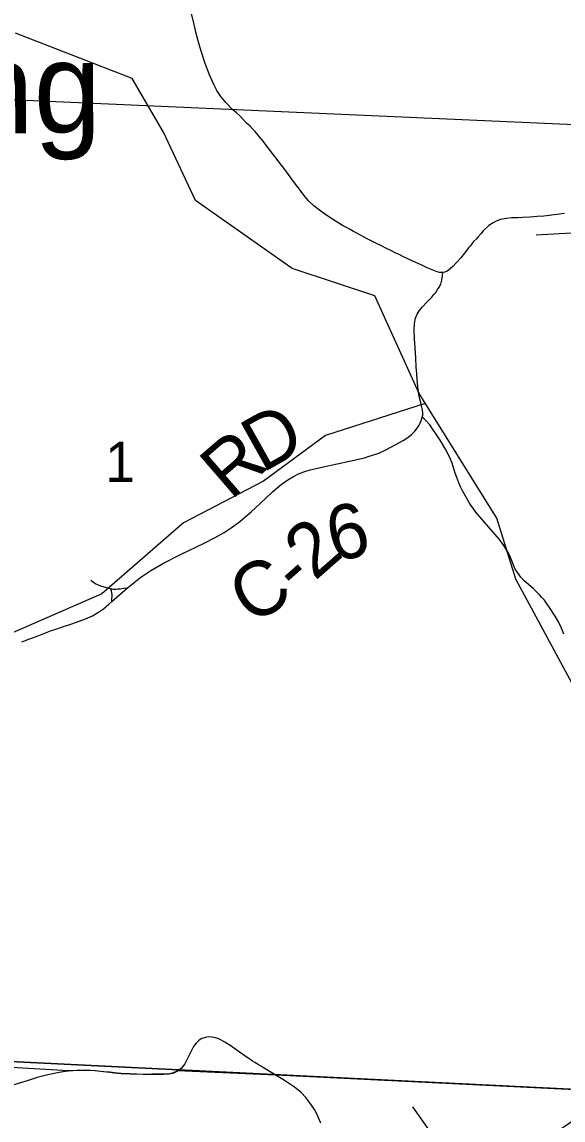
# Model space of a CAD drawing. Extents: x 396.2 to 468.4, y 232.6 to 279.1.
# Drawn here: x 421.28 to 421.844, y 276.238 to 277.383 of the extents above; entities that cross this region are included whole.
import ezdxf

# ---------------------------------------------------------------- set-up
doc = ezdxf.new("R2010")
doc.units = 0
for name, color, linetype in [('Default', 7, 'Continuous'), ('GM_X_County_Road', 7, 'Continuous'), ('GM_X_County_Road_Text', 7, 'Continuous'), ('GM_X_Minor_River', 7, 'Continuous'), ('GM_X_Minor_River_Text', 7, 'Continuous'), ('GM_X_Section', 7, 'Continuous'), ('GM_X_Section_Text', 7, 'Continuous'), ('GM_X_Township', 7, 'Continuous'), ('GM_X_Township_Road', 7, 'Continuous')]:
    doc.layers.add(name, color=color, linetype=linetype)

msp = doc.modelspace()

# ---------------------------------------------------------------- linework, layer by layer
at = {"layer": 'Default'}
msp.add_lwpolyline([(420.82, 276.3196), (421.3281, 276.2897), (421.3374, 276.2902), (421.3462, 276.2904), (421.3559, 276.2899), (421.3682, 276.2886), (421.3714, 276.2883), (421.3763, 276.2876), (421.3831, 276.287), (421.3924, 276.2866), (421.4063, 276.2861), (421.4152, 276.2862), (421.4272, 276.2863), (421.4332, 276.2865), (421.4379, 276.2877), (421.4411, 276.2892), (421.4419, 276.2897), (421.5448, 276.2853), (421.871, 276.2694), (421.9162, 277.0067), (421.9279, 277.1991), (421.9682, 277.8582), (415.7353, 277.8582)], dxfattribs=at)
msp.add_lwpolyline([(421.97, 277.8582), (420.9126, 277.8582), (420.8756, 277.3198), (421.9349, 277.2729), (421.9483, 277.4985)], close=True, dxfattribs=at)
at = {"layer": 'GM_X_County_Road'}
for points in [[(421.7974, 277.1791), (421.7964, 277.1791), (421.7907, 277.1789), (421.7852, 277.1785), (421.7792, 277.1772), (421.7747, 277.1756), (421.7714, 277.174), (421.7669, 277.1709), (421.7611, 277.1655), (421.7585, 277.1624), (421.7555, 277.159), (421.7539, 277.1573), (421.751, 277.1542), (421.749, 277.1519), (421.7476, 277.1499), (421.746, 277.148), (421.7415, 277.1423), (421.7376, 277.1374), (421.734, 277.1331), (421.7292, 277.1282), (421.7265, 277.1257), (421.7247, 277.1244), (421.7233, 277.1234), (421.721, 277.1225), (421.719, 277.1222), (421.7176, 277.122), (421.7156, 277.1222), (421.7131, 277.1227), (421.7114, 277.1233), (421.7061, 277.1254), (421.7027, 277.1269), (421.6971, 277.1296), (421.6937, 277.1311), (421.6909, 277.1324), (421.6869, 277.1343), (421.6824, 277.1364), (421.6779, 277.1385), (421.6734, 277.1407), (421.67, 277.1423), (421.6645, 277.145), (421.66, 277.1471), (421.6534, 277.1504), (421.6512, 277.1515), (421.6463, 277.154), (421.6436, 277.1554), (421.6399, 277.1572), (421.6362, 277.1592), (421.6284, 277.1634), (421.6258, 277.1649), (421.6222, 277.167), (421.6185, 277.169), (421.6142, 277.1712), (421.5999, 277.1802), (421.5954, 277.1833), (421.5902, 277.187), (421.5844, 277.1917), (421.5789, 277.1969), (421.5729, 277.2041), (421.5693, 277.2088), (421.5665, 277.2125), (421.562, 277.2185), (421.5579, 277.2242), (421.5542, 277.2295), (421.5506, 277.234), (421.5489, 277.2362), (421.5471, 277.2386), (421.5423, 277.2449), (421.5378, 277.2508), (421.5367, 277.2522), (421.5333, 277.2566), (421.5314, 277.259), (421.5294, 277.2614), (421.5264, 277.2653), (421.5231, 277.2691), (421.5204, 277.272), (421.5176, 277.275), (421.5142, 277.2779), (421.511, 277.2811), (421.5075, 277.285), (421.5036, 277.2885), (421.4996, 277.2921), (421.4927, 277.2993), (421.4875, 277.3057), (421.4833, 277.3119), (421.48, 277.318), (421.4754, 277.3283), (421.4709, 277.3399), (421.4667, 277.3529), (421.465, 277.3589), (421.4637, 277.3637), (421.4613, 277.3727), (421.4605, 277.3763), (421.4595, 277.3805), (421.4551, 277.3992)], [(421.8458, 277.1834), (421.8297, 277.1814), (421.8242, 277.1808), (421.8173, 277.1803), (421.8095, 277.1798), (421.8025, 277.1793), (421.7974, 277.1791)], [(421.3735, 276.7788), (421.3899, 276.7932), (421.4039, 276.8043), (421.4142, 276.8111), (421.4277, 276.8188), (421.4453, 276.828), (421.4699, 276.8399), (421.4816, 276.8457), (421.4909, 276.8508), (421.4982, 276.8556), (421.5071, 276.8625), (421.5189, 276.8726), (421.534, 276.8865), (421.5413, 276.8933), (421.5503, 276.9009), (421.5572, 276.9059), (421.563, 276.9094), (421.5683, 276.9121), (421.574, 276.9142), (421.5804, 276.9163), (421.5869, 276.9178), (421.5946, 276.9194), (421.6038, 276.9213), (421.6264, 276.9264), (421.6325, 276.9278), (421.6373, 276.9289), (421.6409, 276.93), (421.6455, 276.9315), (421.6521, 276.9338), (421.6596, 276.937), (421.6693, 276.9423), (421.6776, 276.9468), (421.6823, 276.9499), (421.6863, 276.953), (421.6898, 276.9566), (421.692, 276.9597), (421.6941, 276.9627), (421.6949, 276.9643), (421.6961, 276.9667), (421.6967, 276.9688), (421.6974, 276.971), (421.6979, 276.9732), (421.6981, 276.9757), (421.6978, 276.9782), (421.6974, 276.9801), (421.6968, 276.9829), (421.6959, 276.9863), (421.6949, 276.9899), (421.6946, 276.9914), (421.6941, 276.9931), (421.6939, 276.9953), (421.6935, 276.9976), (421.6928, 277.0031), (421.6922, 277.0103), (421.6917, 277.0163), (421.6912, 277.0234), (421.6906, 277.0329), (421.6893, 277.0531), (421.6889, 277.0623), (421.6893, 277.069), (421.6905, 277.0743), (421.6921, 277.0785), (421.6941, 277.0819), (421.6978, 277.0864), (421.7021, 277.091), (421.7075, 277.0964), (421.7096, 277.099), (421.7116, 277.1013), (421.7135, 277.1042), (421.7151, 277.1066), (421.7167, 277.11), (421.7179, 277.1142), (421.7186, 277.1186), (421.719, 277.1222)], [(421.2797, 276.7368), (421.2897, 276.7406), (421.2957, 276.7429), (421.3027, 276.7456), (421.3096, 276.7482), (421.3164, 276.7505), (421.3222, 276.7525), (421.332, 276.7557), (421.3463, 276.7609), (421.3535, 276.7641), (421.3598, 276.7679), (421.3648, 276.7714), (421.3705, 276.7761), (421.3735, 276.7788)], [(421.5443, 276.2852), (421.5422, 276.2865), (421.532, 276.2925), (421.5286, 276.2946), (421.5262, 276.2961), (421.5227, 276.2981), (421.5205, 276.2996), (421.518, 276.3013), (421.5104, 276.3064), (421.5006, 276.3135), (421.4958, 276.3168), (421.4942, 276.3178), (421.4916, 276.3194), (421.486, 276.3224), (421.4819, 276.324), (421.4782, 276.3247), (421.4743, 276.3248), (421.4712, 276.3243), (421.4676, 276.3231), (421.4646, 276.3214), (421.4615, 276.3184), (421.459, 276.3149), (421.456, 276.3092), (421.4525, 276.3022), (421.4498, 276.2968), (421.4464, 276.2923), (421.4437, 276.2901), (421.4421, 276.2891), (421.4414, 276.2887)], [(421.3271, 276.289), (421.3187, 276.2878), (421.3068, 276.2853), (421.2956, 276.2825), (421.2853, 276.2792), (421.267, 276.2735)], [(421.4414, 276.2887), (421.4381, 276.2872), (421.4334, 276.286), (421.4274, 276.2857), (421.4154, 276.2857), (421.4065, 276.2856), (421.3926, 276.286), (421.3833, 276.2865), (421.3765, 276.2871), (421.3716, 276.2878), (421.3684, 276.2881), (421.3562, 276.2894), (421.3464, 276.2898), (421.3377, 276.2897), (421.3284, 276.2892), (421.3271, 276.289)], [(421.5916, 276.235), (421.5902, 276.2382), (421.5878, 276.2439), (421.5849, 276.2491), (421.582, 276.2537), (421.5793, 276.2576), (421.576, 276.2617), (421.571, 276.2668), (421.5643, 276.2724), (421.5538, 276.2793), (421.545, 276.2847), (421.5443, 276.2852)]]:
    msp.add_lwpolyline(points, dxfattribs=at)
at = {"layer": 'GM_X_Minor_River'}
for points in [[(421.8963, 276.6149), (421.7951, 276.8023), (421.7753, 276.8659), (421.6942, 276.9957), (421.6481, 277.0978), (421.5619, 277.1263), (421.4608, 277.1971), (421.4276, 277.2685), (421.3949, 277.3244), (421.2732, 277.3715)], [(422.2928, 277.2843), (422.2562, 277.2635), (422.2441, 277.2578), (422.2156, 277.2589), (422.1974, 277.2676), (422.1747, 277.2726), (422.1501, 277.2756), (422.13, 277.2752), (422.1152, 277.2672), (422.0989, 277.2238), (422.0928, 277.2105), (422.0761, 277.1915), (422.0496, 277.1793), (422.0265, 277.177), (422.0139, 277.1697), (422.0075, 277.1644), (421.9866, 277.1473), (421.962, 277.1514), (421.9374, 277.1643), (421.9082, 277.1662), (421.8164, 277.1608)], [(421.7006, 276.9855), (421.5965, 276.952), (421.5318, 276.9043), (421.4485, 276.8611), (421.3633, 276.787), (421.1829, 276.7084), (421.0566, 276.6936), (420.9975, 276.7147), (420.9769, 276.7483), (420.9031, 276.7643), (420.8288, 276.7238), (420.7251, 276.6432), (420.6532, 276.6296), (420.5642, 276.7268), (420.4872, 276.7473), (420.4757, 276.7567), (420.4039, 276.7925)], [(422.2995, 276.3228), (422.2267, 276.2876), (422.1231, 276.2784), (422.0405, 276.2135), (421.945, 276.2548), (421.8715, 276.2488), (421.7627, 276.1746), (421.7271, 276.1955), (421.6877, 276.2521)]]:
    msp.add_lwpolyline(points, dxfattribs=at)
at = {"layer": 'GM_X_Section'}
for points in [[(421.9349, 277.2729), (421.9181, 277.0115), (421.8725, 276.2694), (420.8243, 276.321), (420.8122, 276.3213), (420.8756, 277.3198)], [(420.8243, 276.321), (421.8725, 276.2694), (421.8607, 276.0303), (421.8429, 275.7758), (421.8262, 275.5154), (421.8083, 275.2473), (421.8081, 275.2441), (420.7452, 275.2968)]]:
    msp.add_lwpolyline(points, close=True, dxfattribs=at)
at = {"layer": 'GM_X_Township'}
msp.add_lwpolyline([(420.82, 276.3196), (421.3281, 276.2897), (421.3374, 276.2902), (421.3462, 276.2904), (421.3559, 276.2899), (421.3682, 276.2886), (421.3714, 276.2883), (421.3763, 276.2876), (421.3831, 276.287), (421.3924, 276.2866), (421.4063, 276.2861), (421.4152, 276.2862), (421.4272, 276.2863), (421.4332, 276.2865), (421.4379, 276.2877), (421.4411, 276.2892), (421.4419, 276.2897), (421.5448, 276.2853), (421.871, 276.2694)], dxfattribs=at)
at = {"layer": 'GM_X_Township_Road'}
for points in [[(421.845, 276.745), (421.8428, 276.7511), (421.8395, 276.7578), (421.8361, 276.7635), (421.8302, 276.7726), (421.8277, 276.7762), (421.8248, 276.7803), (421.8221, 276.7832), (421.8196, 276.7858), (421.816, 276.7897), (421.8136, 276.7923), (421.8084, 276.7967), (421.8038, 276.8006), (421.8003, 276.8043), (421.7968, 276.8091), (421.7945, 276.8126), (421.7887, 276.8265), (421.7861, 276.8319), (421.7827, 276.8375), (421.7781, 276.8435), (421.7619, 276.8619), (421.7532, 276.8722), (421.7511, 276.8751), (421.7488, 276.8782), (421.7467, 276.8816), (421.7449, 276.8845), (421.7395, 276.8943), (421.7375, 276.8986), (421.7356, 276.9028), (421.7335, 276.9083), (421.7319, 276.9126), (421.7304, 276.9174), (421.7285, 276.9233), (421.7259, 276.9297), (421.7217, 276.9377), (421.716, 276.9471), (421.7052, 276.9632), (421.7014, 276.9674), (421.6993, 276.9696), (421.6974, 276.971)], [(421.3518, 276.8011), (421.3546, 276.799), (421.3571, 276.7975), (421.3601, 276.7959), (421.363, 276.7949), (421.3668, 276.7939), (421.3702, 276.793), (421.3724, 276.7925), (421.3751, 276.7919), (421.3777, 276.7918), (421.38, 276.792), (421.3828, 276.7923), (421.3857, 276.7927), (421.3899, 276.7932)], [(421.3735, 276.7788), (421.3738, 276.7816), (421.374, 276.7842), (421.374, 276.7861), (421.3738, 276.7877), (421.3734, 276.79), (421.3724, 276.7925)]]:
    msp.add_lwpolyline(points, dxfattribs=at)

# ---------------------------------------------------------------- texts
at = {"layer": 'GM_X_County_Road_Text'}
for s, rotation, p in [('D', 29.228, (421.5305, 276.9126)), ('R', 40.8386, (421.4977, 276.8838)), ('6', 13.3433, (421.6052, 276.8195)), ('2', 41.2716, (421.5853, 276.7998)), ('C', 30.7877, (421.5185, 276.7537)), ('-', 41.4489, (421.5679, 276.7843))]:
    msp.add_text(s, height=0.0568, rotation=rotation, dxfattribs=at).set_placement(p)
at = {"layer": 'GM_X_Minor_River_Text'}
msp.add_text('Long', height=0.0947, rotation=0.5112, dxfattribs=at).set_placement((421.0812, 277.2655))
at = {"layer": 'GM_X_Section_Text'}
msp.add_text('1', height=0.0419, rotation=0, dxfattribs=at).set_placement((421.3667, 276.9036))

doc.saveas('drawing.dxf')
